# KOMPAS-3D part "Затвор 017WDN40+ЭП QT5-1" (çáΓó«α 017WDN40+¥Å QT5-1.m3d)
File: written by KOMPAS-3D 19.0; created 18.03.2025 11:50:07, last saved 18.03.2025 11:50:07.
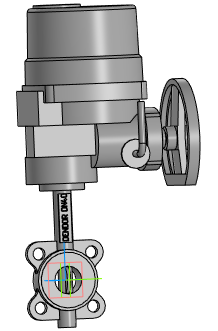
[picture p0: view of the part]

Document properties: Полное имя файла: Затвор 017WDN40+ЭП QT5-1.a3d

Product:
- Part/product: Затвор 017WDN40+ЭП QT5-1
    Масса: 42.1926

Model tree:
1. Операция без истории:1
